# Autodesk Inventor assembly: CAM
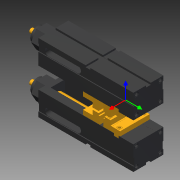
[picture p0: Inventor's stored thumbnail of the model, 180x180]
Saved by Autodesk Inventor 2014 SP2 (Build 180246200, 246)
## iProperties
Created: 2005-05
Part Number: CAM
Document SubType Name: Assembly
Designer: Administrator
Mass: 8690.96 g
Surface Area: 10177 cm^2
Volume: 8690.96 cm^3
Density: 1 g/cm^3
Author: Administrator
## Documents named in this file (3)
- C:\SolidCAM_Temp\PRISMA_AUFSPANNUNG-3\PRISMA_AUFSPANNUNG-3.IAM
- C:\SolidCAM_Temp\PRISMA_AUFSPANNUNG-3\DesignModel.iam
- C:\SolidCAM_Temp\PRISMA_AUFSPANNUNG-3\CAM.IPT
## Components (2 placed, 2 different names)
1. DesignModel:1 [sub-assembly]
2. CAM:1
